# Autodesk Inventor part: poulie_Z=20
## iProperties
Shininess: 64.0
Length Units: 11269
Angle Units: 11279
Time Units: 11290
Mass Units: 11283
Length Display Precision: 3
Angle Display Precision: 2
Compacted: True
Part Number: poulie_Z=20
Document SubType Name: Modeling
Created: 2004-05
Material: Par défaut
Designer: David
Density: 0.0
Volumn: 0.0
Area: 0.0
PropertySet Name: Model Information
Control State: 0
Master: False
Checked Out: False
Author: David
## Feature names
1. Révolution1 [Revolution]
2. Extrusion2
3. Congé2 [Fillet]
4. Réseau circulaire3 [Circular Pattern]
5. Chanfrein1 [Chamfer]
